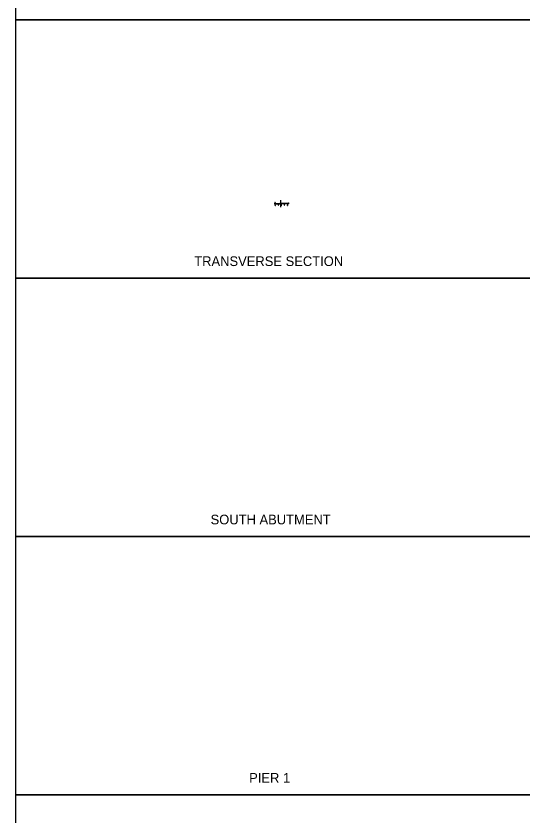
# Model space of a CAD drawing. Extents: x -6598 to 6602, y -3155 to 3145.
# Drawn here: x -6598 to -5030, y -818 to 1657 of the extents above; entities that cross this region are included whole.
import ezdxf

# ---------------------------------------------------------------- set-up
doc = ezdxf.new("R2010")
doc.units = 0
doc.layers.add('BridgeExistingStructure', color=7, linetype='Continuous')
doc.layers.add('ShtPlotShapeBatchPrint', color=7, linetype='Continuous')

msp = doc.modelspace()

# ---------------------------------------------------------------- linework, layer by layer
at = {"layer": 'BridgeExistingStructure'}
for p, q in [((-5796.2, 1076.8), (-5797.2, 1076.8)), ((-5797.2, 1076.8), (-5797.2, 1075.9)), ((-5797.2, 1075.8), (-5797.2, 1075.9)), ((-5797.2, 1075.8), (-5795.6, 1075.8)), ((-5797.2, 1075.8), (-5797.2, 1075.7)), ((-5797.2, 1075.7), (-5797.2, 1075.1)), ((-5797.2, 1075.1), (-5797, 1075.1)), ((-5797, 1075.2), (-5796.9, 1075.1)), ((-5797, 1075.2), (-5797, 1075.1)), ((-5796.9, 1075.1), (-5795.5, 1075)), ((-5795.8, 1078.8), (-5796.7, 1078.8)), ((-5796.7, 1078.8), (-5796.7, 1076.8)), ((-5796.2, 1076.8), (-5795.7, 1076.8)), ((-5795.8, 1078.8), (-5795.8, 1076.8)), ((-5795.7, 1076.8), (-5795.6, 1075.8)), ((-5795.6, 1076), (-5780.6, 1076.2)), ((-5795.6, 1075.8), (-5780.6, 1076)), ((-5795.6, 1075.8), (-5795.6, 1075.8)), ((-5795.5, 1075.1), (-5795.5, 1074.9)), ((-5795.5, 1075.1), (-5794.1, 1075.1)), ((-5794.1, 1075), (-5795.5, 1075)), ((-5794.1, 1074.9), (-5795.5, 1074.9)), ((-5794.1, 1070.6), (-5795.5, 1070.6)), ((-5795.5, 1070.4), (-5795.5, 1070.6)), ((-5794.1, 1070.5), (-5795.5, 1070.5)), ((-5795.5, 1070.4), (-5794.1, 1070.4)), ((-5794.8, 1070.6), (-5794.8, 1074.9)), ((-5794.8, 1070.6), (-5794.8, 1074.9)), ((-5794.1, 1075.2), (-5785.8, 1075.3)), ((-5794.1, 1075.1), (-5794.1, 1075.2)), ((-5794.1, 1075.1), (-5794.1, 1074.9)), ((-5794.1, 1070.4), (-5794.1, 1070.6)), ((-5785.8, 1075.3), (-5785.8, 1075.3)), ((-5785.8, 1075.3), (-5785.8, 1075.1)), ((-5785.8, 1075.3), (-5784.5, 1075.3)), ((-5784.5, 1075.2), (-5785.8, 1075.2)), ((-5784.5, 1075.1), (-5785.8, 1075.1)), ((-5784.5, 1070.7), (-5785.8, 1070.7)), ((-5785.8, 1070.5), (-5785.8, 1070.7)), ((-5784.5, 1070.6), (-5785.8, 1070.6)), ((-5785.8, 1070.5), (-5784.5, 1070.5)), ((-5785.2, 1070.7), (-5785.2, 1075.1)), ((-5785.2, 1070.7), (-5785.2, 1075.1)), ((-5784.5, 1075.3), (-5777.6, 1075.4)), ((-5784.5, 1075.3), (-5784.5, 1075.3)), ((-5784.5, 1075.3), (-5784.5, 1075.1)), ((-5784.5, 1070.5), (-5784.5, 1070.7)), ((-5777.6, 1076.1), (-5777.6, 1076.1)), ((-5776.2, 1075.4), (-5777.6, 1075.4)), ((-5776.2, 1075.4), (-5776.2, 1075.4)), ((-5776.2, 1075.4), (-5776.2, 1075.1)), ((-5776.2, 1075.4), (-5774.9, 1075.4)), ((-5774.9, 1075.3), (-5776.2, 1075.3)), ((-5774.9, 1075.1), (-5776.2, 1075.1)), ((-5774.9, 1070.8), (-5776.2, 1070.8)), ((-5776.2, 1070.6), (-5776.2, 1070.8)), ((-5774.9, 1070.7), (-5776.2, 1070.7)), ((-5776.2, 1070.6), (-5774.9, 1070.6)), ((-5775.6, 1070.8), (-5775.6, 1075.1)), ((-5775.5, 1070.8), (-5775.5, 1075.1)), ((-5774.9, 1075.4), (-5774.9, 1075.4)), ((-5766.6, 1075.3), (-5774.9, 1075.4)), ((-5774.9, 1075.4), (-5774.9, 1075.1)), ((-5774.9, 1070.6), (-5774.9, 1070.8)), ((-5755.5, 1075.9), (-5774.6, 1076.2)), ((-5755.6, 1075.7), (-5774.6, 1076)), ((-5766.6, 1075.2), (-5766.6, 1075.3)), ((-5766.6, 1075.2), (-5766.6, 1075)), ((-5766.6, 1075.2), (-5765.3, 1075.2)), ((-5765.3, 1075.1), (-5766.6, 1075.1)), ((-5765.3, 1075), (-5766.6, 1075)), ((-5765.3, 1070.7), (-5766.6, 1070.7)), ((-5766.6, 1070.5), (-5766.6, 1070.7)), ((-5765.3, 1070.6), (-5766.6, 1070.6)), ((-5766.6, 1070.5), (-5765.3, 1070.5)), ((-5765.9, 1070.7), (-5765.9, 1075)), ((-5765.9, 1070.7), (-5765.9, 1075)), ((-5765.3, 1075.2), (-5765.3, 1075.2)), ((-5757, 1075.1), (-5765.3, 1075.2)), ((-5765.3, 1075.2), (-5765.3, 1075)), ((-5765.3, 1070.5), (-5765.3, 1070.7)), ((-5757, 1075.1), (-5757, 1075.1)), ((-5757, 1075.1), (-5757, 1074.8)), ((-5757, 1075.1), (-5755.6, 1075.1)), ((-5755.6, 1075), (-5757, 1075)), ((-5755.6, 1074.8), (-5757, 1074.8)), ((-5755.6, 1070.5), (-5757, 1070.5)), ((-5757, 1070.3), (-5757, 1070.5)), ((-5755.6, 1070.4), (-5757, 1070.4)), ((-5757, 1070.3), (-5755.6, 1070.3)), ((-5756.3, 1070.5), (-5756.3, 1074.8)), ((-5756.3, 1070.5), (-5756.3, 1074.8)), ((-5755.4, 1076.7), (-5755.6, 1075.8)), ((-5753.9, 1075.7), (-5755.6, 1075.8)), ((-5755.6, 1075.7), (-5755.6, 1075.8)), ((-5754.2, 1075.1), (-5755.6, 1075)), ((-5755.6, 1075.1), (-5755.6, 1074.8)), ((-5755.6, 1070.3), (-5755.6, 1070.5)), ((-5754.9, 1076.8), (-5755.4, 1076.7)), ((-5755.3, 1078.7), (-5754.1, 1078.7)), ((-5755.3, 1078.7), (-5755.3, 1076.7)), ((-5754.9, 1076.8), (-5753.9, 1076.8)), ((-5754.1, 1075.1), (-5754.2, 1075.1)), ((-5754.1, 1078.7), (-5754.1, 1076.8)), ((-5753.9, 1075.1), (-5754.1, 1075.1)), ((-5754.1, 1075.1), (-5754.1, 1075.1)), ((-5753.9, 1076.8), (-5753.9, 1075.8)), ((-5753.9, 1075.7), (-5753.9, 1075.8)), ((-5753.9, 1075.7), (-5753.9, 1075.7)), ((-5753.9, 1075.7), (-5753.9, 1075.1))]:
    msp.add_line(p, q, dxfattribs=at)
msp.add_circle((-5754.7, 1076.2), 0.0833, dxfattribs=at)
for centre in [(-5777.6, 776.2), (-5777.6, 776)]:
    msp.add_arc(centre, 300, 89.427, 90.573, dxfattribs=at)
at = {"layer": 'ShtPlotShapeBatchPrint'}
msp.add_line((-5777.6, 1065), (-5777.6, 1086.6), dxfattribs=at)
for points in [[(-6598.4, 3045.4), (-3398.4, 3045.4), (-3398.4, 1645.4), (-6598.4, 1645.4)], [(-6598.4, 1645.4), (-4998.4, 1645.4), (-4998.4, 845.4), (-6598.4, 845.4)], [(-6598.4, 845.4), (-4998.4, 845.4), (-4998.4, 45.4), (-6598.4, 45.4)], [(-6598.4, 45.4), (-4998.4, 45.4), (-4998.4, -754.6), (-6598.4, -754.6)], [(-6598.4, -754.6), (-3398.4, -754.6), (-3398.4, -1554.6), (-6598.4, -1554.6)]]:
    msp.add_lwpolyline(points, close=True, dxfattribs=at)

# ---------------------------------------------------------------- texts
for s, p in [('TRANSVERSE SECTION', (-6046.1, 882.5)), ('SOUTH ABUTMENT', (-5995.4, 82.5)), ('PIER 1', (-5875.9, -717.5))]:
    msp.add_text(s, height=30, dxfattribs=at).set_placement(p)

doc.saveas('drawing.dxf')
